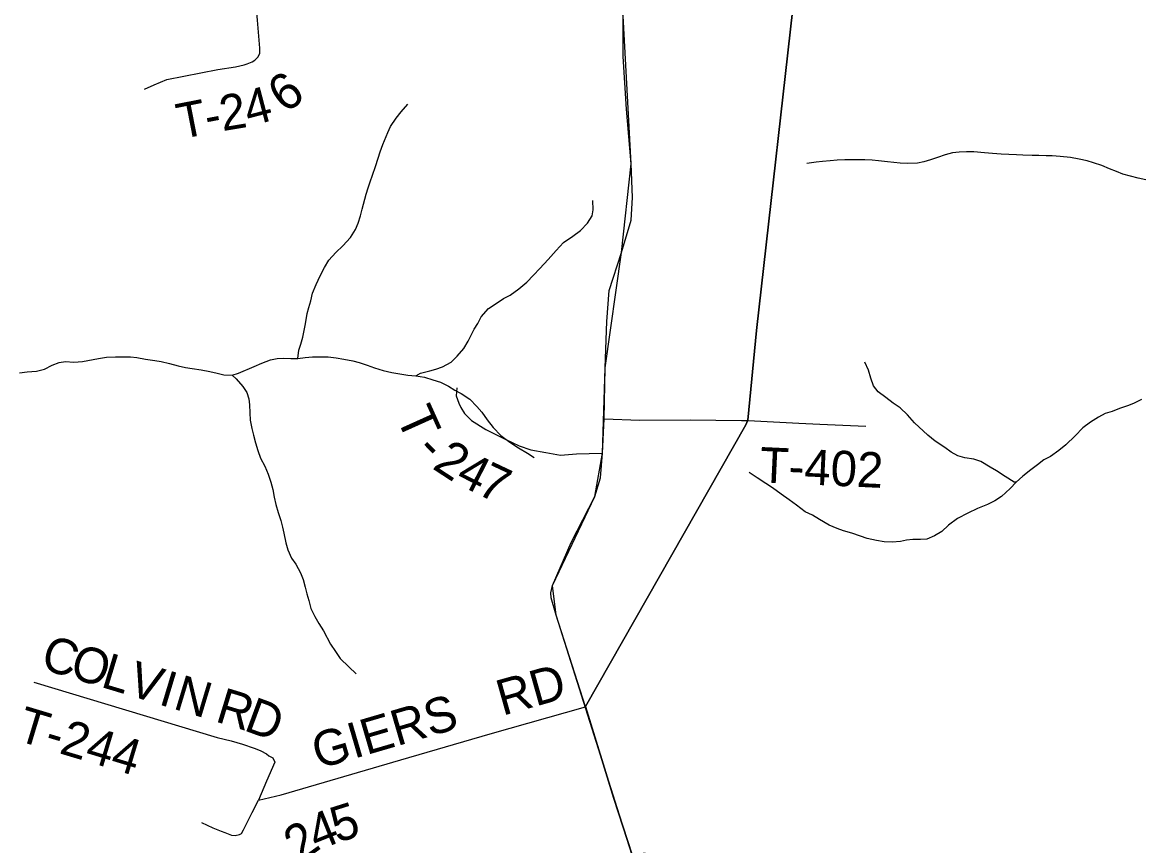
# Model space of a CAD drawing. Extents: x -139 to 835, y 0 to 440.
# Drawn here: x 126.7 to 183.8, y 248.2 to 290.4 of the extents above; entities that cross this region are included whole.
import ezdxf

# ---------------------------------------------------------------- set-up
doc = ezdxf.new("R2010")
doc.units = 0
for name, color, linetype in [('Default', 7, 'Continuous'), ('GM_X_County_Text', 7, 'Continuous'), ('GM_X_Minor_River', 7, 'Continuous'), ('GM_X_State_Route', 7, 'Continuous'), ('GM_X_Township_Road', 7, 'Continuous'), ('GM_X_Township_Road_Text', 7, 'Continuous')]:
    doc.layers.add(name, color=color, linetype=linetype)

msp = doc.modelspace()

# ---------------------------------------------------------------- linework, layer by layer
at = {"layer": 'Default'}
for p, q in [((157.828, 283.115), (157.423, 290.689)), ((157.341, 278.584), (157.828, 283.115)), ((156.505, 272.693), (157.341, 278.584)), ((156.365, 268.323), (156.505, 272.693)), ((155.975, 266.11), (156.365, 268.323)), ((153.809, 261.553), (155.975, 266.11)), ((154, 260.041), (153.809, 261.553)), ((157.887, 247.756), (154, 260.041))]:
    msp.add_line(p, q, dxfattribs=at)
at = {"layer": 'GM_X_County_Text'}
for points in [[(166.338, 293.196), (164.238, 274.594), (163.8, 270.012), (163.693, 269.771), (155.486, 255.368), (156.946, 250.667), (157.88, 247.773)], [(157.88, 247.773), (156.946, 250.667), (155.486, 255.368), (163.693, 269.771), (163.8, 270.012), (164.238, 274.594), (166.338, 293.196)]]:
    msp.add_lwpolyline(points, dxfattribs=at)
at = {"layer": 'GM_X_Minor_River'}
for points in [[(140.79, 273.169), (140.828, 273.592), (140.93, 273.894), (141.045, 274.256), (141.172, 274.933), (141.262, 275.464), (141.351, 275.778), (141.453, 276.117), (141.542, 276.503), (141.72, 276.95), (141.924, 277.385), (142.14, 277.82), (142.369, 278.195), (142.725, 278.581), (143.081, 278.932), (143.475, 279.354), (143.73, 279.765), (143.87, 280.079), (143.984, 280.466), (144.074, 280.792), (144.277, 281.565), (144.379, 281.891), (144.481, 282.193), (144.608, 282.544), (144.749, 282.979), (144.889, 283.401), (144.99, 283.728), (145.13, 284.114), (145.385, 284.718), (145.525, 285.02), (145.818, 285.455), (146.072, 285.769), (146.403, 286.168)], [(184.138, 282.297), (183.756, 282.382), (183.362, 282.479), (182.968, 282.588), (182.651, 282.72), (182.282, 282.853), (181.888, 283.035), (181.469, 283.168), (181.151, 283.264), (180.732, 283.361), (180.3, 283.446), (179.766, 283.494), (179.359, 283.518), (179.041, 283.53), (178.673, 283.543), (178.33, 283.543), (177.847, 283.567), (177.529, 283.579), (177.148, 283.591), (176.741, 283.615), (176.309, 283.652), (175.889, 283.688), (175.356, 283.724), (174.974, 283.724), (174.606, 283.712), (174.262, 283.676), (173.881, 283.579), (173.5, 283.447), (173.131, 283.314), (172.788, 283.217), (172.47, 283.157), (171.962, 283.133), (171.58, 283.145), (171.263, 283.181), (170.932, 283.217), (170.474, 283.278), (170.144, 283.302), (169.775, 283.314), (169.407, 283.326), (169.089, 283.326), (168.759, 283.314), (168.365, 283.302), (168.009, 283.278), (167.615, 283.23), (167.284, 283.194), (166.814, 283.133)], [(146.814, 272.274), (147.056, 272.419), (147.526, 272.54), (147.844, 272.624), (148.175, 272.733), (148.632, 272.975), (148.937, 273.277), (149.268, 273.675), (149.497, 274.05), (149.803, 274.654), (149.981, 274.956), (150.159, 275.294), (150.528, 275.717), (150.871, 275.947), (151.303, 276.237), (151.634, 276.406), (152.092, 276.72), (152.498, 277.07), (152.829, 277.432), (153.16, 277.771), (153.579, 278.218), (153.999, 278.677), (154.368, 279.1), (154.851, 279.414), (155.245, 279.703), (155.602, 280.078), (155.831, 280.465), (155.894, 280.767), (155.869, 281.25)], [(126.554, 272.433), (126.948, 272.481), (127.419, 272.518), (127.825, 272.614), (128.232, 272.82), (128.575, 272.965), (128.906, 273.001), (129.325, 272.977), (129.783, 273.001), (130.596, 273.17), (131.003, 273.23), (131.461, 273.242), (132.236, 273.242), (132.554, 273.206), (132.999, 273.133), (133.469, 273.061), (133.799, 273.012), (134.219, 272.904), (134.664, 272.783), (135.045, 272.71), (135.375, 272.65), (135.845, 272.589), (136.278, 272.505), (136.659, 272.408), (137.002, 272.324), (137.434, 272.311), (137.752, 272.408), (138.553, 272.746), (138.947, 272.927), (139.379, 273.097), (139.722, 273.169), (140.04, 273.181), (140.434, 273.157), (140.79, 273.169), (141.159, 273.205), (141.54, 273.241), (141.883, 273.253), (142.328, 273.241), (142.747, 273.193), (143.129, 273.12), (143.599, 273.036), (143.929, 272.951), (144.323, 272.818), (144.705, 272.685), (145.149, 272.552), (145.594, 272.443), (146.001, 272.371), (146.408, 272.31), (146.814, 272.274), (147.259, 272.202), (147.691, 272.069), (148.072, 271.948), (148.492, 271.742), (148.809, 271.549)], [(177.507, 266.845), (177.405, 266.845), (176.96, 267.135), (176.516, 267.413), (176.185, 267.607), (175.715, 267.897), (175.347, 268.006), (174.889, 268.09), (174.533, 268.187), (174.19, 268.38), (173.86, 268.61), (173.377, 268.936), (172.996, 269.238), (172.323, 269.879), (171.954, 270.278), (171.586, 270.64), (171.217, 270.882), (170.849, 271.16), (170.455, 271.462), (170.227, 271.764), (170.087, 272.15), (169.96, 272.561), (169.77, 272.972)], [(137.434, 272.311), (137.637, 272.13), (137.98, 271.731), (138.171, 271.417), (138.272, 271.103), (138.31, 270.789), (138.323, 270.39), (138.348, 270.016), (138.437, 269.581), (138.525, 269.243), (138.627, 268.844), (138.741, 268.457), (138.868, 268.071), (139.096, 267.648), (139.274, 267.249), (139.401, 266.838), (139.503, 266.464), (139.579, 266.065), (139.667, 265.702), (139.781, 265.292), (139.908, 264.881), (139.997, 264.543), (140.061, 264.228), (140.175, 263.733), (140.276, 263.37), (140.454, 262.948), (140.682, 262.646), (140.924, 262.198), (141.063, 261.86), (141.165, 261.461), (141.241, 261.135), (141.342, 260.785), (141.444, 260.374), (141.647, 259.975), (141.863, 259.613), (142.104, 259.238), (142.459, 258.562), (142.714, 258.175), (142.955, 257.824), (143.387, 257.402), (143.768, 257.039)], [(148.809, 271.549), (149.14, 271.38), (149.572, 271.078), (149.94, 270.715), (150.194, 270.413), (150.461, 270.027), (150.778, 269.628), (151.172, 269.217), (151.617, 268.879), (152.062, 268.601), (152.532, 268.323), (152.862, 268.093)], [(183.928, 271.061), (183.521, 270.868), (183.203, 270.747), (182.796, 270.602), (182.428, 270.457), (182.072, 270.349), (181.729, 270.155), (181.309, 269.902), (180.927, 269.612), (180.533, 269.201), (180.05, 268.742), (179.694, 268.464), (179.262, 268.15), (178.931, 267.981), (178.6, 267.727), (178.257, 267.474), (177.863, 267.147), (177.507, 266.845), (177.214, 266.519), (176.769, 266.109), (176.426, 265.879), (176.044, 265.698), (175.536, 265.492), (175.04, 265.251), (174.519, 264.985), (174.061, 264.647), (173.718, 264.321), (173.336, 264.091), (172.942, 263.922), (172.624, 263.91), (172.23, 263.91), (171.912, 263.874), (171.595, 263.801), (171.175, 263.765), (170.769, 263.79), (170.375, 263.862), (169.904, 263.959), (169.561, 264.08), (169.104, 264.237), (168.684, 264.358), (168.367, 264.466)], [(168.367, 264.466), (167.947, 264.636), (167.464, 264.926), (167.109, 265.143), (166.727, 265.324), (166.283, 265.663), (165.902, 265.941), (165.495, 266.231), (165.05, 266.545), (164.707, 266.775), (164.263, 267.065), (163.869, 267.331)]]:
    msp.add_lwpolyline(points, dxfattribs=at)
at = {"layer": 'GM_X_State_Route'}
for points in [[(155.494, 255.352), (154, 260.041), (153.734, 260.918), (153.723, 261.18), (153.809, 261.553), (154.76, 263.76), (155.975, 266.11), (156.256, 267.059), (156.365, 268.323), (156.444, 270.074), (156.505, 272.693), (156.591, 275.057), (156.703, 276.637), (157.341, 278.584), (157.836, 280.243), (157.891, 281.401), (157.828, 283.115), (157.59, 285.906), (157.414, 288.612), (157.423, 290.689), (156.545, 293.294), (156.46, 293.609)], [(158.54, 247.865), (157.887, 247.756), (156.953, 250.65), (155.494, 255.352)]]:
    msp.add_lwpolyline(points, dxfattribs=at)
at = {"layer": 'GM_X_Township_Road'}
msp.add_line((167.474, 269.81), (169.821, 269.706), dxfattribs=at)
for points in [[(138.201, 288.234), (138.451, 288.328), (138.592, 288.411), (138.746, 288.579), (138.836, 288.759), (138.839, 289.024), (138.716, 290.461), (138.683, 290.859), (138.689, 291.39), (138.82, 291.738), (139.192, 292.144), (139.525, 292.455), (139.844, 292.68), (140.011, 292.872), (140.418, 293.012), (140.912, 292.983), (141.684, 292.902), (142.38, 292.798), (143.089, 292.742), (143.583, 292.737), (144.116, 292.72), (144.774, 292.712)], [(132.948, 286.927), (133.432, 287.163), (134.094, 287.422), (136.698, 287.937), (137.599, 288.072), (138.044, 288.176), (138.201, 288.234)], [(148.919, 271.654), (148.889, 271.256), (149.024, 270.881), (149.123, 270.651), (149.31, 270.347), (149.661, 269.994), (150.403, 269.539), (151.386, 269.034), (152.104, 268.689), (152.698, 268.489), (153.469, 268.348), (154.215, 268.22), (155.027, 268.284), (155.687, 268.301), (156.365, 268.323)], [(156.444, 270.074), (158.266, 270.011), (160.851, 270.028), (163.471, 269.999)], [(163.471, 269.999), (163.807, 269.995), (166.401, 269.858), (167.474, 269.81)], [(127.292, 256.611), (136.663, 253.785), (137.383, 253.609), (137.952, 253.434), (138.209, 253.352)], [(138.781, 250.578), (139.925, 250.855), (146.053, 252.636), (150.618, 253.974), (155.494, 255.352)], [(138.209, 253.352), (138.305, 253.321), (138.596, 253.222), (138.898, 253.098), (139.188, 252.95), (139.301, 252.84), (139.502, 252.742), (139.601, 252.523), (139.185, 251.551), (138.781, 250.578)], [(135.853, 249.427), (136.445, 249.167), (136.862, 248.994), (137.051, 248.919), (137.392, 248.795), (137.581, 248.769), (137.81, 248.827), (137.899, 248.874), (138.003, 249.054), (138.444, 249.942), (138.781, 250.578)]]:
    msp.add_lwpolyline(points, dxfattribs=at)

# ---------------------------------------------------------------- texts
at = {"layer": 'GM_X_Township_Road_Text'}
for s, height, rotation, p in [('6', 1.859, 36.4162, (140.139, 285.661)), ('2', 1.811, 9.3223, (136.933, 284.788)), ('4', 1.817, 14.74, (138.289, 285.021)), ('T', 1.812, 11.0601, (134.787, 284.372)), ('-', 1.812, 10.8034, (136.18, 284.644)), ('T', 1.898, 294.2492, (145.783, 270.2)), ('-', 1.876, 314.3472, (146.729, 268.393)), ('2', 1.853, 326.8841, (147.607, 267.566)), ('T-402', 1.8061, 357.3384, (164.374, 266.834)), ('4', 1.84, 333.2032, (148.774, 266.82)), ('7', 1.836, 334.7398, (149.86, 266.272)), ('C', 1.821, 343.1862, (127.565, 257.317)), ('O', 1.821, 343.1873, (129.055, 256.867)), ('L', 1.821, 343.1862, (130.652, 256.385)), ('V', 1.821, 343.1873, (132.009, 255.975)), ('I', 1.821, 343.1902, (133.605, 255.492)), ('N', 1.821, 343.1873, (134.35, 255.267)), ('RD', 1.8189, 15.7451, (151.248, 254.886)), ('R', 1.821, 342.9747, (136.504, 254.616)), ('D', 1.827, 339.7292, (137.964, 254.17)), ('GIERS', 1.8199, 16.3166, (141.829, 252.157)), ('T-244', 1.8206, 343.2212, (126.331, 253.655)), ('4', 1.83, 21.9597, (141.752, 247.96)), ('5', 1.822, 17.4646, (142.793, 248.382)), ('2', 1.858, 35.7986, (140.926, 247.346))]:
    msp.add_text(s, height=height, rotation=rotation, dxfattribs=at).set_placement(p)

doc.saveas('drawing.dxf')
